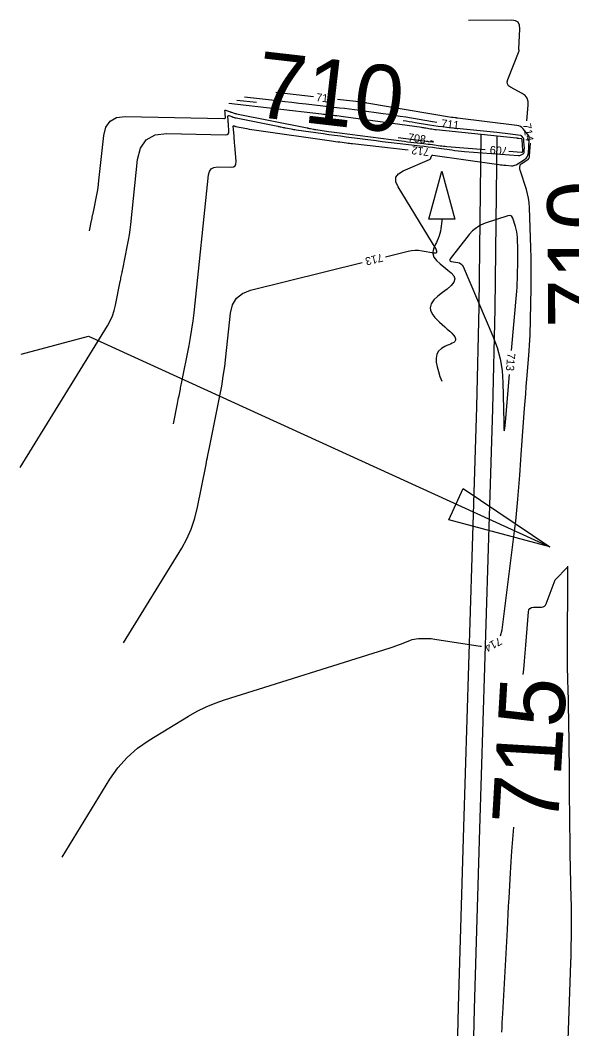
# Model space of a CAD drawing. Extents: x -361782338 to 28259792, y -263199453 to 8342113.
# Drawn here: x 1403607 to 1403883, y 578042 to 578546 of the extents above; entities that cross this region are included whole.
import ezdxf

# ---------------------------------------------------------------- set-up
doc = ezdxf.new("R2010")
doc.units = 0
for name, color, linetype in [('DT_X_Contour_Minor', 7, 'Continuous'), ('Level 19', 7, 'Continuous'), ('Level 40', 7, 'Continuous'), ('Level 56', 7, 'Continuous')]:
    doc.layers.add(name, color=color, linetype=linetype)

msp = doc.modelspace()

# ---------------------------------------------------------------- linework, layer by layer
at = {"layer": 'DT_X_Contour_Minor'}
for points in [[(1403860.33, 578496.05), (1403861.09, 578503.89), (1403861.04, 578505.75), (1403860.5, 578507.34), (1403859.48, 578508.68), (1403857.98, 578509.77), (1403852.27, 578512.89), (1403851.26, 578513.63), (1403850.69, 578514.54), (1403850.55, 578515.6), (1403850.85, 578516.81), (1403856.57, 578531.13), (1403856.59, 578531.21), (1403856.59, 578531.29), (1403856.57, 578531.36), (1403856.53, 578531.43), (1403856.37, 578531.65), (1403856.34, 578531.7), (1403856.32, 578531.75), (1403856.31, 578531.81), (1403856.31, 578531.87), (1403856.9, 578542.07), (1403856.74, 578543.98), (1403856, 578545.34), (1403854.67, 578546.14), (1403852.77, 578546.4), (1403831.18, 578546.2)], [(1403815.32, 578495.27), (1403813.23, 578495.6), (1403799.92, 578497.85), (1403797.07, 578498.32), (1403794.21, 578498.77), (1403791.35, 578499.2), (1403788.49, 578499.61), (1403776.77, 578501.23), (1403774.26, 578501.57), (1403771.75, 578501.89), (1403769.23, 578502.2), (1403766.71, 578502.49), (1403749.98, 578504.39), (1403746.43, 578504.79), (1403742.89, 578505.2), (1403739.35, 578505.6), (1403735.8, 578506.01), (1403719.27, 578507.91)], [(1403753.76, 578508.08), (1403734.89, 578510.22)], [(1403851.42, 578480.85), (1403857.72, 578480.36), (1403857.79, 578480.36), (1403857.86, 578480.37), (1403857.92, 578480.39), (1403857.99, 578480.42), (1403858.19, 578480.55), (1403858.23, 578480.58), (1403858.26, 578480.61), (1403858.28, 578480.65), (1403858.29, 578480.7), (1403858.31, 578481.01), (1403858.31, 578481.07), (1403858.32, 578481.14), (1403858.32, 578481.2), (1403858.31, 578481.27), (1403858, 578486.65), (1403857.99, 578486.71), (1403857.97, 578486.77), (1403857.95, 578486.82), (1403857.91, 578486.87), (1403857.79, 578487.03), (1403857.76, 578487.06), (1403857.72, 578487.08), (1403857.69, 578487.1), (1403857.65, 578487.11), (1403856.32, 578487.27), (1403856.04, 578487.31), (1403855.75, 578487.34), (1403855.47, 578487.37), (1403855.18, 578487.4), (1403815.08, 578491.58), (1403814.35, 578491.66), (1403813.63, 578491.75), (1403812.91, 578491.86), (1403812.19, 578491.97), (1403809.85, 578492.37), (1403809.35, 578492.45), (1403808.84, 578492.53), (1403808.34, 578492.61), (1403807.83, 578492.68), (1403768.72, 578498.09), (1403767.62, 578498.23), (1403766.53, 578498.38), (1403765.44, 578498.51), (1403764.35, 578498.64), (1403760.77, 578499.04), (1403760.01, 578499.13), (1403759.24, 578499.22), (1403758.48, 578499.3), (1403757.71, 578499.39), (1403711.41, 578504.71)], [(1403725.21, 578505.18), (1403715.34, 578506.31)], [(1403789.67, 578428.15), (1403800.97, 578430.95), (1403802.73, 578431.29), (1403804.49, 578431.44), (1403806.26, 578431.41), (1403808.04, 578431.19), (1403813.85, 578430.18), (1403814.86, 578430.13), (1403815.39, 578430.4), (1403815.45, 578430.99), (1403815.03, 578431.91), (1403795.96, 578463.12), (1403794.87, 578465.66), (1403794.93, 578467.85), (1403796.15, 578469.66), (1403798.51, 578471.1), (1403811.7, 578476.74), (1403811.95, 578476.88), (1403812.16, 578477.07), (1403812.33, 578477.29), (1403812.44, 578477.56), (1403812.74, 578478.51), (1403812.82, 578478.69), (1403812.94, 578478.8), (1403813.1, 578478.86), (1403813.29, 578478.86), (1403846.3, 578474.24), (1403847.18, 578474.12), (1403848.05, 578474.02), (1403848.93, 578473.93), (1403849.81, 578473.85), (1403852.67, 578473.63), (1403853.28, 578473.62), (1403853.86, 578473.71), (1403854.42, 578473.9), (1403854.95, 578474.17), (1403859.17, 578476.74), (1403859.97, 578477.35), (1403860.56, 578478.09), (1403860.94, 578478.96), (1403861.12, 578479.95), (1403861.6, 578486.51), (1403861.61, 578486.72), (1403861.61, 578486.93), (1403861.61, 578487.15), (1403861.6, 578487.36), (1403861.56, 578488.05), (1403861.54, 578488.19), (1403861.5, 578488.33), (1403861.44, 578488.46), (1403861.36, 578488.57), (1403858.53, 578492.03), (1403857.88, 578492.69), (1403857.14, 578493.2), (1403856.32, 578493.55), (1403855.41, 578493.75), (1403825.73, 578497.46), (1403825.42, 578497.5), (1403825.12, 578497.53), (1403824.81, 578497.57), (1403824.5, 578497.6), (1403823.5, 578497.71), (1403823.28, 578497.73), (1403823.07, 578497.76), (1403822.85, 578497.79), (1403822.64, 578497.82), (1403780.38, 578504.96), (1403779.99, 578505.02), (1403779.59, 578505.08), (1403779.2, 578505.14), (1403778.81, 578505.2), (1403777.52, 578505.38), (1403777.24, 578505.41), (1403776.96, 578505.45), (1403776.69, 578505.48), (1403776.41, 578505.52), (1403765.69, 578506.73)], [(1403607.09, 578322.81), (1403650.67, 578393.64), (1403652.04, 578396.1), (1403653.18, 578398.65), (1403654.08, 578401.28), (1403654.75, 578404.01), (1403657.1, 578415.71), (1403657.23, 578416.34), (1403657.35, 578416.96), (1403657.48, 578417.59), (1403657.61, 578418.21), (1403658.02, 578420.26), (1403658.1, 578420.69), (1403658.19, 578421.13), (1403658.28, 578421.57), (1403658.37, 578422.01), (1403660.76, 578433.94), (1403661.24, 578436.5), (1403661.67, 578439.07), (1403662.03, 578441.65), (1403662.33, 578444.24), (1403665.73, 578476.71), (1403667.17, 578482.5), (1403670.11, 578486.6), (1403674.54, 578489.01), (1403680.47, 578489.71), (1403709.73, 578489.11), (1403710.55, 578489.21), (1403711.11, 578489.55), (1403711.41, 578490.12), (1403711.46, 578490.94), (1403711.2, 578494.25), (1403711.16, 578494.78), (1403711.12, 578495.32), (1403711.07, 578495.85), (1403711.03, 578496.39), (1403710.89, 578498.21), (1403710.9, 578498.49), (1403711, 578498.66), (1403711.19, 578498.72), (1403711.47, 578498.67), (1403712.88, 578498.19), (1403712.92, 578498.18), (1403712.95, 578498.17), (1403712.98, 578498.16), (1403713.02, 578498.15), (1403713.14, 578498.11), (1403713.16, 578498.1), (1403713.18, 578498.09), (1403713.2, 578498.09), (1403713.22, 578498.08), (1403713.28, 578498.06), (1403713.29, 578498.05), (1403713.31, 578498.05), (1403713.32, 578498.04), (1403713.33, 578498.04), (1403713.41, 578498.01), (1403713.43, 578498.01), (1403713.45, 578498), (1403713.47, 578498), (1403713.48, 578497.99), (1403714.29, 578497.72), (1403714.46, 578497.66), (1403714.64, 578497.61), (1403714.81, 578497.57), (1403714.99, 578497.53), (1403735.87, 578493.37), (1403736.25, 578493.29), (1403736.62, 578493.22), (1403737, 578493.14), (1403737.37, 578493.07), (1403738.59, 578492.82), (1403738.86, 578492.77), (1403739.12, 578492.72), (1403739.38, 578492.67), (1403739.64, 578492.61), (1403742.54, 578492.04), (1403743.16, 578491.92), (1403743.78, 578491.81), (1403744.4, 578491.71), (1403745.03, 578491.61), (1403758.49, 578489.71), (1403761.37, 578489.3), (1403764.26, 578488.91), (1403767.15, 578488.52), (1403770.04, 578488.14), (1403785.11, 578486.18), (1403788.11, 578485.8), (1403791.1, 578485.43), (1403794.1, 578485.07), (1403797.1, 578484.73), (1403806.89, 578483.64), (1403808.99, 578483.4), (1403811.09, 578483.14), (1403813.18, 578482.87), (1403815.27, 578482.59), (1403822.8, 578481.53), (1403824.41, 578481.32), (1403826.03, 578481.13), (1403827.64, 578480.96), (1403829.26, 578480.82)], [(1403641.76, 578441.04), (1403642.8, 578446.2), (1403642.89, 578446.64), (1403642.98, 578447.08), (1403643.07, 578447.52), (1403643.15, 578447.96), (1403643.44, 578449.4), (1403643.5, 578449.71), (1403643.57, 578450.01), (1403643.63, 578450.32), (1403643.69, 578450.63), (1403645.37, 578459.02), (1403645.71, 578460.82), (1403646.01, 578462.62), (1403646.26, 578464.44), (1403646.48, 578466.26), (1403648.83, 578488.78), (1403649.88, 578492.99), (1403652.01, 578495.96), (1403655.24, 578497.71), (1403659.54, 578498.23), (1403708.96, 578497.2), (1403709.31, 578497.24), (1403709.56, 578497.39), (1403709.69, 578497.64), (1403709.72, 578498), (1403709.6, 578499.44), (1403709.58, 578499.68), (1403709.56, 578499.91), (1403709.54, 578500.15), (1403709.53, 578500.38), (1403709.47, 578501.14), (1403709.47, 578501.28), (1403709.52, 578501.36), (1403709.62, 578501.39), (1403709.75, 578501.36), (1403712.3, 578500.51), (1403712.31, 578500.5), (1403712.32, 578500.5), (1403712.33, 578500.5), (1403712.34, 578500.49), (1403712.37, 578500.48), (1403712.38, 578500.48), (1403712.39, 578500.48), (1403712.39, 578500.47), (1403712.4, 578500.47), (1403712.42, 578500.47), (1403712.42, 578500.46), (1403712.42, 578500.46), (1403712.43, 578500.46), (1403712.43, 578500.46), (1403712.59, 578500.41), (1403712.62, 578500.4), (1403712.66, 578500.38), (1403712.69, 578500.37), (1403712.73, 578500.36), (1403714.04, 578499.92), (1403714.33, 578499.83), (1403714.61, 578499.75), (1403714.9, 578499.67), (1403715.19, 578499.61), (1403750.47, 578492.58), (1403750.65, 578492.54), (1403750.83, 578492.5), (1403751.01, 578492.47), (1403751.19, 578492.43), (1403751.77, 578492.32), (1403751.9, 578492.29), (1403752.02, 578492.27), (1403752.15, 578492.24), (1403752.27, 578492.22), (1403753.65, 578491.94), (1403753.95, 578491.88), (1403754.24, 578491.83), (1403754.54, 578491.78), (1403754.84, 578491.74), (1403761.26, 578490.83), (1403762.64, 578490.64), (1403764.01, 578490.45), (1403765.39, 578490.26), (1403766.77, 578490.08), (1403797.7, 578486.06), (1403799.23, 578485.86), (1403800.77, 578485.67), (1403802.3, 578485.49), (1403803.84, 578485.32), (1403808.87, 578484.76), (1403809.94, 578484.63), (1403811.02, 578484.5), (1403812.09, 578484.36), (1403813.17, 578484.21), (1403817.02, 578483.67), (1403817.85, 578483.56), (1403818.68, 578483.47), (1403819.51, 578483.38), (1403820.34, 578483.31), (1403839.46, 578481.8)], [(1403683.67, 578344.57), (1403685.71, 578354.74), (1403685.91, 578355.73), (1403686.11, 578356.73), (1403686.31, 578357.72), (1403686.51, 578358.72), (1403687.16, 578361.98), (1403687.3, 578362.67), (1403687.44, 578363.37), (1403687.58, 578364.07), (1403687.72, 578364.77), (1403691.54, 578383.78), (1403692.31, 578387.86), (1403692.98, 578391.96), (1403693.56, 578396.07), (1403694.04, 578400.2), (1403701.24, 578469.06), (1403701.68, 578470.83), (1403702.58, 578472.08), (1403703.94, 578472.82), (1403705.75, 578473.04), (1403712.42, 578472.9), (1403713.66, 578473.05), (1403714.51, 578473.56), (1403714.97, 578474.44), (1403715.05, 578475.69), (1403714.4, 578483.85), (1403714.31, 578484.99), (1403714.22, 578486.13), (1403714.13, 578487.27), (1403714.04, 578488.4), (1403713.63, 578493.52), (1403713.64, 578493.6), (1403713.67, 578493.65), (1403713.72, 578493.66), (1403713.8, 578493.65), (1403714.09, 578493.55), (1403714.15, 578493.53), (1403714.21, 578493.51), (1403714.27, 578493.49), (1403714.34, 578493.47), (1403714.58, 578493.39), (1403714.63, 578493.37), (1403714.68, 578493.35), (1403714.74, 578493.34), (1403714.79, 578493.33), (1403720.43, 578492.21), (1403721.64, 578491.97), (1403722.85, 578491.76), (1403724.07, 578491.56), (1403725.28, 578491.38), (1403762.65, 578486.09), (1403763.7, 578485.94), (1403764.75, 578485.8), (1403765.8, 578485.66), (1403766.86, 578485.52), (1403770.29, 578485.07), (1403771.03, 578484.98), (1403771.76, 578484.89), (1403772.5, 578484.8), (1403773.24, 578484.72), (1403801.04, 578481.62)], [(1403829.26, 578480.82), (1403856.14, 578478.7), (1403856.5, 578478.7), (1403856.85, 578478.75), (1403857.18, 578478.86), (1403857.5, 578479.02), (1403858.52, 578479.64), (1403858.71, 578479.79), (1403858.85, 578479.97), (1403858.95, 578480.18), (1403858.99, 578480.42), (1403859.1, 578481.94), (1403859.12, 578482.26), (1403859.13, 578482.59), (1403859.12, 578482.91), (1403859.11, 578483.24), (1403858.91, 578486.58), (1403858.87, 578486.86), (1403858.79, 578487.14), (1403858.67, 578487.39), (1403858.5, 578487.63), (1403857.89, 578488.38), (1403857.75, 578488.52), (1403857.59, 578488.63), (1403857.41, 578488.71), (1403857.21, 578488.75), (1403850.83, 578489.55), (1403849.46, 578489.72), (1403848.09, 578489.88), (1403846.72, 578490.03), (1403845.35, 578490.18), (1403820.36, 578492.78), (1403818.18, 578493.02), (1403816, 578493.3), (1403813.82, 578493.62), (1403811.65, 578493.97), (1403804.57, 578495.16), (1403803.05, 578495.41), (1403801.53, 578495.65), (1403800.01, 578495.88), (1403798.48, 578496.1)], [(1403796.05, 578487.79), (1403810.28, 578485.94), (1403810.36, 578485.93), (1403810.43, 578485.92), (1403810.51, 578485.91), (1403810.59, 578485.9), (1403810.84, 578485.87), (1403810.89, 578485.87), (1403810.95, 578485.86), (1403811, 578485.85), (1403811.06, 578485.84), (1403811.25, 578485.82), (1403811.29, 578485.81), (1403811.33, 578485.81), (1403811.38, 578485.8), (1403811.42, 578485.8), (1403813.27, 578485.65), (1403813.57, 578485.64), (1403813.67, 578485.66), (1403813.58, 578485.71), (1403813.29, 578485.8), (1403812.29, 578486.08)], [(1403847.22, 578238.7), (1403848.06, 578241.76), (1403854.37, 578292.35), (1403854.81, 578296), (1403855.2, 578299.66), (1403855.56, 578303.32), (1403855.87, 578306.99), (1403856.83, 578318.97), (1403857.04, 578321.54), (1403857.23, 578324.11), (1403857.42, 578326.68), (1403857.61, 578329.25), (1403859.24, 578352.36), (1403859.5, 578356), (1403859.78, 578359.65), (1403860.07, 578363.29), (1403860.37, 578366.92), (1403861.39, 578378.81), (1403861.59, 578381.36), (1403861.75, 578383.91), (1403861.87, 578386.46), (1403861.95, 578389.01), (1403862.51, 578412.53), (1403862.59, 578417.57), (1403862.6, 578422.61), (1403862.54, 578427.65), (1403862.41, 578432.69), (1403861.73, 578452.79), (1403861.57, 578455.09), (1403861.25, 578457.36), (1403860.76, 578459.6), (1403860.12, 578461.82), (1403856.95, 578471.42), (1403856.86, 578471.75), (1403856.81, 578472.09), (1403856.81, 578472.43), (1403856.84, 578472.77), (1403857.02, 578473.9), (1403857.08, 578474.12), (1403857.19, 578474.32), (1403857.33, 578474.49), (1403857.52, 578474.63), (1403860.41, 578476.4), (1403860.95, 578476.82), (1403861.36, 578477.33), (1403861.63, 578477.92), (1403861.75, 578478.6), (1403862.2, 578484.85)], [(1403852.75, 578381.28), (1403855.3, 578410.94), (1403855.46, 578412.96), (1403855.58, 578414.98), (1403855.68, 578417.01), (1403855.74, 578419.03), (1403855.9, 578425.65), (1403855.92, 578427.07), (1403855.93, 578428.49), (1403855.91, 578429.91), (1403855.87, 578431.33), (1403855.65, 578437.91), (1403855.55, 578439.27), (1403855.37, 578440.6), (1403855.08, 578441.92), (1403854.7, 578443.22), (1403853.31, 578447.44), (1403852.93, 578448.2), (1403852.41, 578448.65), (1403851.73, 578448.8), (1403850.9, 578448.65), (1403839.56, 578444.88), (1403837.23, 578443.92), (1403835.12, 578442.66), (1403833.23, 578441.09), (1403831.55, 578439.22), (1403822.11, 578427.1), (1403821.83, 578426.61), (1403821.82, 578426.23), (1403822.08, 578425.96), (1403822.62, 578425.81)], [(1403658.68, 578235.11), (1403687.85, 578282.51), (1403690.44, 578287.16), (1403692.59, 578291.97), (1403694.3, 578296.96), (1403695.57, 578302.12), (1403700.01, 578324.25), (1403700.25, 578325.43), (1403700.48, 578326.61), (1403700.72, 578327.79), (1403700.96, 578328.97), (1403701.73, 578332.84), (1403701.9, 578333.66), (1403702.07, 578334.49), (1403702.23, 578335.32), (1403702.4, 578336.15), (1403706.93, 578358.7), (1403707.84, 578363.55), (1403708.64, 578368.4), (1403709.32, 578373.28), (1403709.89, 578378.18), (1403712.16, 578399.88), (1403713.16, 578404.09), (1403715.16, 578407.42), (1403718.18, 578409.87), (1403722.21, 578411.43), (1403778.03, 578425.26)], [(1403822.62, 578425.81), (1403825.79, 578425.32), (1403826.68, 578425.07), (1403827.43, 578424.64), (1403828.04, 578424.02), (1403828.5, 578423.22), (1403843.43, 578388.49), (1403845.54, 578382.86), (1403847.07, 578377.11), (1403848.04, 578371.24), (1403848.43, 578365.24), (1403848.79, 578345.45), (1403848.9, 578342.27), (1403849.09, 578341.2), (1403849.34, 578342.25), (1403849.67, 578345.42), (1403851.73, 578369.32)], [(1403858.58, 578219.39), (1403858.81, 578221.91), (1403859.16, 578225.97), (1403859.49, 578230.03), (1403859.82, 578234.09), (1403861.13, 578250.61), (1403861.37, 578251.67), (1403861.89, 578252.43), (1403862.68, 578252.89), (1403863.76, 578253.05), (1403867.74, 578253.08), (1403868.52, 578253.18), (1403869.17, 578253.49), (1403869.67, 578253.99), (1403870.04, 578254.69), (1403874.46, 578266.62), (1403880.77, 578272.99)], [(1403880.77, 578273.59), (1403880.77, 578273.41), (1403880.77, 578273.3), (1403880.77, 578273.2), (1403880.77, 578273.09), (1403880.77, 578272.99), (1403880.51, 578228.45), (1403880.51, 578226.98), (1403880.52, 578225.5), (1403880.54, 578224.03), (1403880.57, 578222.56), (1403880.7, 578217.75), (1403880.72, 578216.71), (1403880.75, 578215.68), (1403880.77, 578214.65), (1403880.79, 578213.62), (1403881.32, 578185.86), (1403881.41, 578180.48), (1403881.49, 578175.1), (1403881.55, 578169.71), (1403881.6, 578164.33), (1403881.74, 578143.35), (1403881.76, 578141.28), (1403881.78, 578139.21), (1403881.8, 578137.14), (1403881.82, 578135.07), (1403881.9, 578128.31), (1403881.92, 578126.86), (1403881.95, 578125.41), (1403881.98, 578123.96), (1403882.01, 578122.51), (1403882.41, 578107.47), (1403882.48, 578104.25), (1403882.51, 578101.02), (1403882.52, 578097.8), (1403882.5, 578094.57), (1403882.28, 578077.15), (1403882.28, 578076.96), (1403882.27, 578076.77), (1403882.27, 578076.59), (1403882.27, 578076.4), (1403882.26, 578075.79), (1403882.26, 578075.66), (1403882.25, 578075.52), (1403882.25, 578075.39), (1403882.24, 578075.26), (1403880.6, 578027.15)], [(1403628.01, 578128.09), (1403651.98, 578167.03), (1403655.99, 578172.78), (1403660.58, 578177.94), (1403665.76, 578182.52), (1403671.52, 578186.51), (1403691.29, 578198.59), (1403695.59, 578201.04), (1403700.02, 578203.22), (1403704.57, 578205.11), (1403709.25, 578206.74), (1403792.04, 578232.67), (1403793.46, 578233.13), (1403794.86, 578233.62), (1403796.25, 578234.13), (1403797.63, 578234.67), (1403802.13, 578236.48), (1403803.1, 578236.82), (1403804.1, 578237.07), (1403805.11, 578237.22), (1403806.14, 578237.28), (1403810.59, 578237.34), (1403811.54, 578237.34), (1403812.49, 578237.29), (1403813.43, 578237.2), (1403814.38, 578237.08), (1403837.1, 578233.5), (1403837.68, 578233.5)], [(1403847.89, 578040.65), (1403848, 578042.96), (1403848.11, 578045.27), (1403848.22, 578047.58), (1403848.34, 578049.88), (1403850.62, 578091.91), (1403850.83, 578095.8), (1403851.04, 578099.7), (1403851.26, 578103.6), (1403851.48, 578107.5), (1403852.21, 578120.23), (1403852.37, 578122.96), (1403852.55, 578125.69), (1403852.73, 578128.42), (1403852.93, 578131.14), (1403853.81, 578143.08)]]:
    msp.add_lwpolyline(points, dxfattribs=at)
at = {"layer": 'Level 40'}
for p, q in [((1403607.64, 578379.46), (1403641.26, 578388.47)), ((1403641.26, 578388.47), (1403871.88, 578283.11)), ((1403821.41, 578296.74), (1403828.54, 578312.36)), ((1403828.54, 578312.36), (1403871.88, 578283.11)), ((1403871.88, 578283.11), (1403821.41, 578296.74))]:
    msp.add_line(p, q, dxfattribs=at)
at = {"layer": 'Level 56'}
for p, q in [((1403811.42, 578446.89), (1403817.9, 578470.89)), ((1403817.9, 578470.89), (1403824.3, 578446.88)), ((1403824.3, 578446.88), (1403811.42, 578446.89))]:
    msp.add_line(p, q, dxfattribs=at)
for points in [[(1403799.72, 576951.13), (1403799.37, 577003.24), (1403799.52, 577053.24), (1403800.45, 577093.03), (1403801.13, 577118.22), (1403803.77, 577203.2), (1403806.32, 577303.59), (1403809.79, 577453.55), (1403811.89, 577528.32), (1403813.35, 577578.3), (1403815.32, 577653.47), (1403817.33, 577718.44), (1403820.35, 577828.2), (1403822.42, 577903.37), (1403824.98, 578003.34), (1403826.21, 578053.33), (1403828.88, 578143.09), (1403833.01, 578278.03), (1403835.33, 578353.19), (1403836.58, 578403.18), (1403837.59, 578489.24)], [(1403807.71, 576950.11), (1403807.36, 577002.22), (1403807.51, 577052.22), (1403808.43, 577092.01), (1403809.12, 577117.2), (1403811.75, 577202.18), (1403814.31, 577302.57), (1403817.77, 577452.53), (1403819.88, 577527.3), (1403821.33, 577577.28), (1403823.31, 577652.45), (1403825.32, 577717.42), (1403828.34, 577827.18), (1403830.4, 577902.36), (1403832.96, 578002.32), (1403834.2, 578052.31), (1403836.87, 578142.07), (1403841, 578277.01), (1403843.32, 578352.18), (1403844.57, 578402.16), (1403845.58, 578488.22)]]:
    msp.add_lwpolyline(points, dxfattribs=at)
msp.add_spline([(1403817.8, 578446.91), (1403817.79, 578445.96), (1403815.53, 578436.09), (1403813.35, 578429.84), (1403824.36, 578417.1), (1403811.97, 578402.57), (1403824.33, 578385.75), (1403817.63, 578382.36), (1403817.79, 578365.89)], degree=3, dxfattribs=at)

# ---------------------------------------------------------------- texts
at = {"layer": 'Level 19'}
for s, height, rotation, p in [('710', 33, 353.4434, (1403723.66, 578498.23)), ('713', 4, 353.53, (1403754.85, 578505.95)), ('711', 4, 353.0425, (1403817.39, 578492.91)), ('714', 4, 279.4712, (1403858.39, 578494.45)), ('708', 4, 352.0092, (1403800.76, 578485.96)), ('712', 4, 173.1946, (1403811.85, 578482.37)), ('709', 4, 175.4805, (1403850.95, 578482.9)), ('710', 33, 90.3957, (1403904.01, 578392.66)), ('713', 4, 193.9165, (1403787.91, 578429.77)), ('713', 4, 265.0902, (1403850.65, 578380.13)), ('714', 4, 208.5918, (1403846.48, 578238.2)), ('715', 33, 86.6239, (1403875.86, 578143.44))]:
    msp.add_text(s, height=height, rotation=rotation, dxfattribs=at).set_placement(p)

doc.saveas('drawing.dxf')
